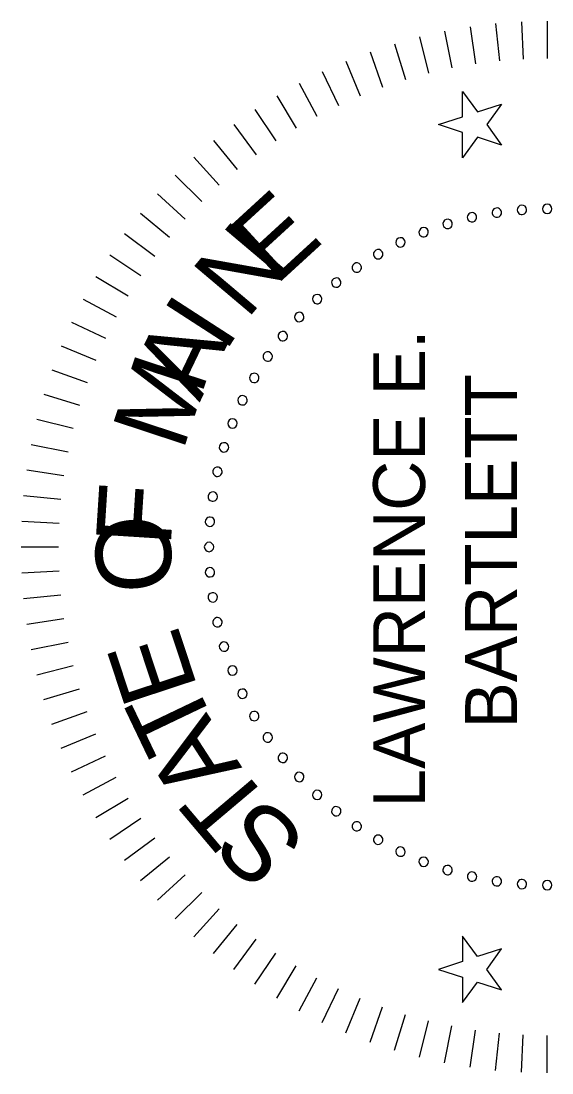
# Model space of a CAD drawing. Extents: x 916251 to 917164, y 328941 to 329491.
# Drawn here: x 917043.76 to 917063.85, y 329315.1 to 329354.93 of the extents above; entities that cross this region are included whole.
import ezdxf

# ---------------------------------------------------------------- set-up
doc = ezdxf.new("R2010")
doc.units = 0
doc.layers.add('Default', color=7, linetype='Continuous')
doc.layers.add('elec-detail-ext-post-mtd-meter-panel', color=7, linetype='Continuous')

# ---------------------------------------------------------------- blocks, each defined once
blk = doc.blocks.new('STAMP')
at = {"layer": 'Default'}
for p, q in [((-0.000781, 0.009427), (-0.000725, 0.008861)), ((-0.000391, 0.009455), (-0.000363, 0.008887)), ((0, 0.009465), (0, 0.008896)), ((0.000391, 0.009455), (0.000363, 0.008887)), ((0.000781, 0.009427), (0.000725, 0.008861)), ((-0.001554, 0.009312), (-0.001443, 0.008754)), ((-0.001169, 0.009379), (-0.001085, 0.008816)), ((0.001169, 0.009379), (0.001085, 0.008816)), ((0.001554, 0.009312), (0.001443, 0.008754)), ((-0.002312, 0.009122), (-0.002147, 0.008578)), ((-0.001935, 0.009226), (-0.001797, 0.008674)), ((0.001935, 0.009226), (0.001797, 0.008674)), ((0.002312, 0.009122), (0.002147, 0.008578)), ((-0.002683, 0.008999), (-0.002492, 0.008464)), ((0.002683, 0.008999), (0.002492, 0.008464)), ((-0.003048, 0.008859), (-0.00283, 0.008333)), ((0.003048, 0.008859), (0.00283, 0.008333)), ((-0.003406, 0.0087), (-0.003162, 0.008186)), ((0.003406, 0.0087), (0.003162, 0.008186)), ((-0.003755, 0.008525), (-0.003487, 0.008023)), ((0.003755, 0.008525), (0.003487, 0.008023)), ((-0.004095, 0.008332), (-0.003802, 0.007844)), ((0.004095, 0.008332), (0.003802, 0.007844)), ((-0.004425, 0.008123), (-0.004109, 0.00765)), ((0.004425, 0.008123), (0.004109, 0.00765)), ((-0.004745, 0.007898), (-0.004406, 0.007441)), ((0.004745, 0.007898), (0.004406, 0.007441)), ((-0.005053, 0.007657), (-0.004692, 0.007217)), ((0.005053, 0.007657), (0.004692, 0.007217)), ((-0.005349, 0.007402), (-0.004967, 0.00698)), ((0.005349, 0.007402), (0.004967, 0.00698)), ((-0.005632, 0.007132), (-0.00523, 0.00673)), ((0.005632, 0.007132), (0.00523, 0.00673)), ((-0.005902, 0.006849), (-0.00548, 0.006467)), ((0.005902, 0.006849), (0.00548, 0.006467)), ((-0.006157, 0.006553), (-0.005717, 0.006192)), ((0.006157, 0.006553), (0.005717, 0.006192)), ((-0.006398, 0.006245), (-0.005941, 0.005906)), ((0.006398, 0.006245), (0.005941, 0.005906)), ((-0.006623, 0.005925), (-0.00615, 0.005609)), ((0.006623, 0.005925), (0.00615, 0.005609)), ((-0.006832, 0.005595), (-0.006344, 0.005302)), ((0.006832, 0.005595), (0.006344, 0.005302)), ((-0.007025, 0.005255), (-0.006523, 0.004987)), ((0.007025, 0.005255), (0.006523, 0.004987)), ((-0.0072, 0.004906), (-0.006686, 0.004662)), ((0.0072, 0.004906), (0.006686, 0.004662)), ((-0.007359, 0.004548), (-0.006833, 0.00433)), ((0.007359, 0.004548), (0.006833, 0.00433)), ((-0.007499, 0.004183), (-0.006964, 0.003992)), ((0.007499, 0.004183), (0.006964, 0.003992)), ((-0.007622, 0.003812), (-0.007078, 0.003647)), ((0.007622, 0.003812), (0.007078, 0.003647)), ((-0.007726, 0.003435), (-0.007174, 0.003297)), ((0.007726, 0.003435), (0.007174, 0.003297)), ((-0.007812, 0.003054), (-0.007254, 0.002943)), ((-0.006396, 0.003148), (-0.006515, 0.002783)), ((-0.006278, 0.002783), (-0.006396, 0.003148)), ((0.006278, 0.002783), (0.006396, 0.003148)), ((0.006396, 0.003148), (0.006515, 0.002783)), ((0.007812, 0.003054), (0.007254, 0.002943)), ((-0.006515, 0.002783), (-0.006899, 0.002783)), ((-0.006899, 0.002783), (-0.006589, 0.002557)), ((-0.005894, 0.002783), (-0.006278, 0.002783)), ((-0.006204, 0.002557), (-0.005894, 0.002783)), ((0.006204, 0.002557), (0.005894, 0.002783)), ((0.005894, 0.002783), (0.006278, 0.002783)), ((0.006515, 0.002783), (0.006899, 0.002783)), ((0.006899, 0.002783), (0.006589, 0.002557)), ((-0.007879, 0.002669), (-0.007316, 0.002585)), ((-0.006589, 0.002557), (-0.006707, 0.002191)), ((-0.006086, 0.002191), (-0.006204, 0.002557)), ((0.006086, 0.002191), (0.006204, 0.002557)), ((0.006589, 0.002557), (0.006707, 0.002191)), ((0.007879, 0.002669), (0.007316, 0.002585)), ((-0.006707, 0.002191), (-0.006396, 0.002417)), ((-0.006396, 0.002417), (-0.006086, 0.002191)), ((0.006396, 0.002417), (0.006086, 0.002191)), ((0.006707, 0.002191), (0.006396, 0.002417)), ((-0.007927, 0.002281), (-0.007361, 0.002225)), ((0.007927, 0.002281), (0.007361, 0.002225)), ((-0.007955, 0.001891), (-0.007387, 0.001863)), ((0.007955, 0.001891), (0.007387, 0.001863)), ((-0.007965, 0.0015), (-0.007396, 0.0015)), ((0.007965, 0.0015), (0.007396, 0.0015))]:
    blk.add_line(p, q, dxfattribs=at)
for points in [[(-0.006278, 0.002783), (-0.006396, 0.003148), (-0.006515, 0.002783), (-0.006899, 0.002783), (-0.006589, 0.002557), (-0.006707, 0.002191), (-0.006396, 0.002417), (-0.006086, 0.002191), (-0.006204, 0.002557), (-0.005894, 0.002783)], [(0.006278, 0.002783), (0.006396, 0.003148), (0.006515, 0.002783), (0.006899, 0.002783), (0.006589, 0.002557), (0.006707, 0.002191), (0.006396, 0.002417), (0.006086, 0.002191), (0.006204, 0.002557), (0.005894, 0.002783)]]:
    blk.add_lwpolyline(points, close=True, dxfattribs=at)
for centre, start, end in [((0, 0.00662), 0, 180), ((-0.001139, 0.006492), 12.8571, 192.8571), ((-0.000763, 0.006563), 8.5714, 188.5714), ((-0.000763, 0.006563), 188.5714, 8.5714), ((-0.000383, 0.006606), 4.2857, 184.2857), ((-0.000383, 0.006606), 184.2857, 4.2857), ((0, 0.00662), 180, 0), ((0.000383, 0.006606), 355.7143, 175.7143), ((0.000383, 0.006606), 175.7143, 355.7143), ((0.000763, 0.006563), 171.4286, 351.4286), ((0.000763, 0.006563), 351.4286, 171.4286), ((0.001139, 0.006492), 347.1429, 167.1429), ((-0.001509, 0.006393), 17.1429, 197.1429), ((-0.001509, 0.006393), 197.1429, 17.1429), ((-0.001139, 0.006492), 192.8571, 12.8571), ((0.001139, 0.006492), 167.1429, 347.1429), ((0.001509, 0.006393), 162.8571, 342.8571), ((0.001509, 0.006393), 342.8571, 162.8571), ((-0.001871, 0.006266), 21.4286, 201.4286), ((-0.001871, 0.006266), 201.4286, 21.4286), ((0.001871, 0.006266), 158.5714, 338.5714), ((0.001871, 0.006266), 338.5714, 158.5714), ((-0.002222, 0.006113), 25.7143, 205.7143), ((-0.002222, 0.006113), 205.7143, 25.7143), ((0.002222, 0.006113), 154.2857, 334.2857), ((0.002222, 0.006113), 334.2857, 154.2857), ((-0.00256, 0.005934), 30, 210), ((-0.00256, 0.005934), 210, 30), ((0.00256, 0.005934), 150, 330), ((0.00256, 0.005934), 330, 150), ((-0.002884, 0.005731), 34.2857, 214.2857), ((-0.002884, 0.005731), 214.2857, 34.2857), ((0.002884, 0.005731), 145.7143, 325.7143), ((0.002884, 0.005731), 325.7143, 145.7143), ((-0.003193, 0.005503), 38.5714, 218.5714), ((-0.003193, 0.005503), 218.5714, 38.5714), ((0.003193, 0.005503), 141.4286, 321.4286), ((0.003193, 0.005503), 321.4286, 141.4286), ((-0.003483, 0.005254), 42.8571, 222.8571), ((-0.003483, 0.005254), 222.8571, 42.8571), ((0.003483, 0.005254), 137.1429, 317.1429), ((0.003483, 0.005254), 317.1429, 137.1429), ((-0.003754, 0.004983), 47.1429, 227.1429), ((-0.003754, 0.004983), 227.1429, 47.1429), ((0.003754, 0.004983), 132.8571, 312.8571), ((0.003754, 0.004983), 312.8571, 132.8571), ((-0.004003, 0.004693), 51.4286, 231.4286), ((-0.004003, 0.004693), 231.4286, 51.4286), ((0.004003, 0.004693), 128.5714, 308.5714), ((0.004003, 0.004693), 308.5714, 128.5714), ((-0.004231, 0.004384), 55.7143, 235.7143), ((-0.004231, 0.004384), 235.7143, 55.7143), ((0.004231, 0.004384), 124.2857, 304.2857), ((0.004231, 0.004384), 304.2857, 124.2857), ((-0.004434, 0.00406), 60, 240), ((-0.004434, 0.00406), 240, 60), ((0.004434, 0.00406), 120, 300), ((0.004434, 0.00406), 300, 120), ((-0.004613, 0.003722), 64.2857, 244.2857), ((-0.004613, 0.003722), 244.2857, 64.2857), ((0.004613, 0.003722), 115.7143, 295.7143), ((0.004613, 0.003722), 295.7143, 115.7143), ((-0.004766, 0.003371), 68.5714, 248.5714), ((-0.004766, 0.003371), 248.5714, 68.5714), ((0.004766, 0.003371), 111.4286, 291.4286), ((0.004766, 0.003371), 291.4286, 111.4286), ((-0.004893, 0.003009), 72.8571, 252.8571), ((-0.004893, 0.003009), 252.8571, 72.8571), ((0.004893, 0.003009), 107.1429, 287.1429), ((0.004893, 0.003009), 287.1429, 107.1429), ((-0.004992, 0.002639), 77.1429, 257.1429), ((-0.004992, 0.002639), 257.1429, 77.1429), ((0.004992, 0.002639), 102.8571, 282.8571), ((0.004992, 0.002639), 282.8571, 102.8571), ((-0.005063, 0.002263), 81.4286, 261.4286), ((-0.005063, 0.002263), 261.4286, 81.4286), ((0.005063, 0.002263), 98.5714, 278.5714), ((0.005063, 0.002263), 278.5714, 98.5714), ((-0.005106, 0.001883), 85.7143, 265.7143), ((-0.005106, 0.001883), 265.7143, 85.7143), ((0.005106, 0.001883), 94.2857, 274.2857), ((0.005106, 0.001883), 274.2857, 94.2857), ((-0.00512, 0.0015), 90, 270), ((-0.00512, 0.0015), 270, 90), ((0.00512, 0.0015), 90, 270), ((0.00512, 0.0015), 270, 90)]:
    blk.add_arc(centre, 0.0000711, start, end, dxfattribs=at)
for s, rotation, p in [('O', 3.6538, (-0.000663, 0.007159)), ('F', 356.3462, (-0.000007, 0.007201)), ('E', 18.2692, (-0.002136, 0.006786)), ('M', 341.7308, (0.001431, 0.007019)), ('T', 25.5769, (-0.002759, 0.006487)), ('A', 334.4231, (0.002185, 0.006762)), ('A', 32.8846, (-0.003342, 0.006114)), ('I', 327.1154, (0.002925, 0.006384)), ('T', 40.1923, (-0.003928, 0.005629)), ('N', 319.8077, (0.003426, 0.006054)), ('S', 47.5, (-0.004421, 0.005096)), ('E', 312.5, (0.003944, 0.005617))]:
    blk.add_text(s, height=0.001138, rotation=rotation, dxfattribs=at).set_placement(p)
for s, height, p in [('LAWRENCE E.', 0.00078513, (-0.003944, 0.00335)), ('BARTLETT', 0.0007851, (-0.002748, 0.001958))]:
    blk.add_text(s, height=height, dxfattribs=at).set_placement(p)

msp = doc.modelspace()

# ---------------------------------------------------------------- block references
at = {"layer": 'elec-detail-ext-post-mtd-meter-panel', "xscale": 2499.999999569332, "yscale": 2499.999999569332, "rotation": 90}
msp.add_blockref('STAMP', (917067.421, 329335.013), dxfattribs=at)

doc.saveas('drawing.dxf')
